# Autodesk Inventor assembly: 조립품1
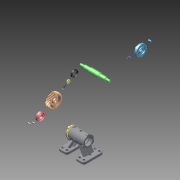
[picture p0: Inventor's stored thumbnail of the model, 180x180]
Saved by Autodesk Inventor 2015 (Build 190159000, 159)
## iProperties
Created: 2026-04
Part Number: 조립품1
Document SubType Name: Assembly
Designer: User
Author: User
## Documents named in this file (16)
- C:\Users\User\Desktop\760403V1015\조립품1.iam
- C:\Users\User\Desktop\760403V1015\760403V1015.ipt
- C:\Users\User\Desktop\760403V1015\Imported Components\6각 구멍붙이 볼트 M4x12\6각 구멍붙이 볼트 M4x12.ipt
- C:\Users\User\Desktop\760403V1015\Imported Components\그리스 니플 M6x0,75\그리스 니플 M6x0,75.ipt
- C:\Users\User\Desktop\760403V1015\Imported Components\깊은 홈 볼 베어링 6004\깊은 홈 볼 베어링 6004.ipt
- C:\Users\User\Desktop\760403V1015\Imported Components\스퍼 기어\스퍼 기어.ipt
- C:\Users\User\Desktop\760403V1015\Imported Components\스프링 와셔 M4\스프링 와셔 M4.ipt
- C:\Users\User\Desktop\760403V1015\Imported Components\실링\실링.ipt
- C:\Users\User\Desktop\760403V1015\Imported Components\엔드 캡\엔드 캡.ipt
- C:\Users\User\Desktop\760403V1015\Imported Components\오일 실 20 35 8\오일 실 20 35 8.ipt
- C:\Users\User\Desktop\760403V1015\Imported Components\축\축.ipt
- C:\Users\User\Desktop\760403V1015\Imported Components\커버\커버.ipt
- C:\Users\User\Desktop\760403V1015\Imported Components\평 와셔 M4\평 와셔 M4.ipt
- C:\Users\User\Desktop\760403V1015\Imported Components\평행 키 4x4x14\평행 키 4x4x14.ipt
- C:\Users\User\Desktop\760403V1015\Imported Components\플랜지\플랜지.ipt
- C:\Users\User\Desktop\760403V1015\Imported Components\플러그 M6x0,75\플러그 M6x0,75.ipt
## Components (5 placed, 5 different names)
1. 760403V1015:2
2. 6각 구멍붙이 볼트 M4x12:3
3. 그리스 니플 M6x0,75:3
4. 플랜지:3
5. 플러그 M6x0,75:3
